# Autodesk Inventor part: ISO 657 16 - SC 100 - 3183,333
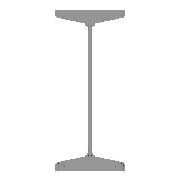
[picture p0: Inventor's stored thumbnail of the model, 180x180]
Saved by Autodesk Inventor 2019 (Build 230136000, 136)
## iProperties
_CCFamilyMember: 1
_CCFamilyDisplayName: ISO 657/16 - 1980 - Poutres en acier laminées à chaud - Partie 16: profilés en H (série métrique) - Cotes et propriétés de section
_FrameMemberDoc: Frame Member File
_Version: 15.0.0
_GetPNFromCC: 1
Created: 2018-07
Part Number: ISO 657 16 - SC 100 - 3183,333
Material: Acier, doux
Description: Poutres en acier laminées à chaud - Partie 16: profilés en H (série métrique) - Cotes et propriétés de section
Document SubType Name: Modeling
Standard: ISO
Designer: Fabian Perrée
Standard Revision: First edition 1980-02-15
Standards Organization: ISO
Language: fr-FR
Size Designation: SC 100
Categories: <MemberInstance><Categories><Category DisplayName="Profilés" InternalName="089c4875-fa83-4c05-b084-43b9cc11f5ed" Mnemonic="GRDR"><CategoryParameter DisplayName=
Stock Number: SC 100
Density: 7.85 g/cm^3
Appearance: Semi-poli
IsCustomPart: 1
G_W: 100,000 mm
G_H: 100,000 mm
+B7F31D84-8E7F-44BF-867D-18DAA1A1DD99+DETAILDECOUPE1: Angle de coupe 67,38 deg
G_L: 3183,333 mm
+959F2517-F8C4-4F8C-BEA7-D48C5E0A7FF3+DETAILDECOUPE2: Angle de coupe 67,38 deg
Author: Fabian Perrée
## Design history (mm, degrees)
node "Plan de départ"
node "Plan de fin"
sketch "Esquisse"
  geometry: L1 (-3, 0)-(-3, -26.266); L2 (-13.33, -38.149)-(-44.835, -42.577); L3 (-50, -48.518)-(-50, -50); L4 (-50, -50)-(0, -50); L5 (-26.5, -50)-(-26.5, -40); L6 (-61.333, 0)-(81.777, 0); L7 (0, 0)-(0, -50); L8 (0, -60)-(0, 80); L9 (3, 0)-(3, -26.266); L10 (13.33, -38.149)-(44.835, -42.577); L11 (50, -48.518)-(50, -50); L12 (50, -50)-(0, -50); L13 (-3, 0)-(0, 0); L14 (-3, 0)-(-3, 26.266); L15 (-13.33, 38.149)-(-44.835, 42.577); L16 (-50, 48.518)-(-50, 50); L17 (-50, 50)-(0, 50); L18 (50, 48.518)-(50, 50); L19 (13.33, 38.149)-(44.835, 42.577); L20 (3, 0)-(3, 26.266); L21 (50, 50)-(0, 50); L22 (0, 108)-(0, -88) reference; L23 (-89.955, 0)-(110.399, 0) reference; A1 r 6 centre (-44, 48.518) between (-50, 48.518) and (-44.835, 42.577); A2 r 6 centre (44, 48.518) between (44.835, 42.577) and (50, 48.518); A3 r 6 centre (44, -48.518) between (50, -48.518) and (44.835, -42.577); A4 r 6 centre (-44, -48.518) between (-44.835, -42.577) and (-50, -48.518); A5 r 12 centre (-15, 26.266) between (-3, 26.266) and (-13.33, 38.149); A6 r 12 centre (15, 26.266) between (13.33, 38.149) and (3, 26.266); A7 r 12 centre (15, -26.266) between (3, -26.266) and (13.33, -38.149); A8 r 12 centre (-15, -26.266) between (-13.33, -38.149) and (-3, -26.266); 14 further points
  constraints: 42 end point, 24 point on line, 17 symmetric about line, 16 point on circle, 16 tangent, 8 centre point, 6 equal radius, 4 collinear, 2 perpendicular, 12 other
  dimensions: "d1" = 10 vertical distance of L3.end L5.end (= G_T1); "d2" = 23.5 distance between parallel lines of L5 L3 (= -0.25 x G_T + 0.25 x G_W); "d3" = 3 distance between parallel lines of L1 L7 (= 0.5 x G_T); "d4" = 50 distance between parallel lines of L7 L3 (= 0.5 x G_W); "d9" = 50 distance from line of L1.start L4 (= 0.5 x G_H); "d14" = 98 deg angle of L2 L1 (= G_NG); "d15" = 6 radius of A1 (= G_ER); "d16" = 12 radius of A5 (= G_IR)
extrude "Corps" new body sketch "Esquisse" stored distance "d5" = 3183.33333 (= G_L); taper "d6" = 0 deg
node "Driven Length"
  sketch "Sketch3"
    geometry: L1 (0, 0)-(10, 0) reference
    constraints: 2 end point, 1 horizontal
  workplane "Work Plane3"
  sketch "Sketch4"
    geometry: L1 (-2, 66.667)-(12, 66.667) reference; L2 (-2, 3250)-(12, 3250) reference
    dimensions: "d20" = 3183.33333 distance between parallel lines of L1 L2 (derived)
node "Plan de construction4"
feature "Scission1"
node "Plan de construction5"
feature "Scission2"
body "Solid1"
other parameters: "G_W" = 100 (= G_H) [user parameter; used in 2 equation terms], "G_H" = 100 [user parameter; used in 2 equation terms], "G_T" = 6 [user parameter; used in 2 equation terms], "G_T1" = 10 [user parameter; used in 1 equation term], "G_L" = 3183.33333 (= d20) [user parameter; used in 1 equation term], "G_ER" = 6 [user parameter; used in 1 equation term], "G_IR" = 12 [user parameter; used in 1 equation term], "G_NG" = 98 deg [user parameter; used in 1 equation term], "G_OFFSET_START" = -66.66667 [user parameter; used in 1 equation term], "G_OFFSET_END" = 0 [user parameter; used in 1 equation term], "d17" = 66.66667 (= -G_OFFSET_START), "d19" = 90 deg
